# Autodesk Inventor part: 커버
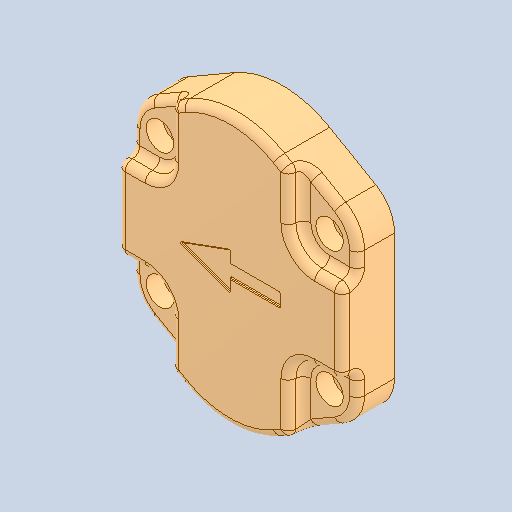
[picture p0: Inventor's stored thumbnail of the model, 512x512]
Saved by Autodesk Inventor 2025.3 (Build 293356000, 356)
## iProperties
Created: 2025-10
Part Number: 커버
Material: 알루미늄 6061
Document SubType Name: Modeling
Designer: PC-04
Density: 2.7 g/cm^3
Appearance: 기본값
Author: jhkim
Sending System: Autodesk Inventor 2026
Preprocessor: ST-DEVELOPER v20.1
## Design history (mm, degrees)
feature "솔리드2"
node "솔리드1"
